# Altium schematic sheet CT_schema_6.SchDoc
size 287 x 160 mm
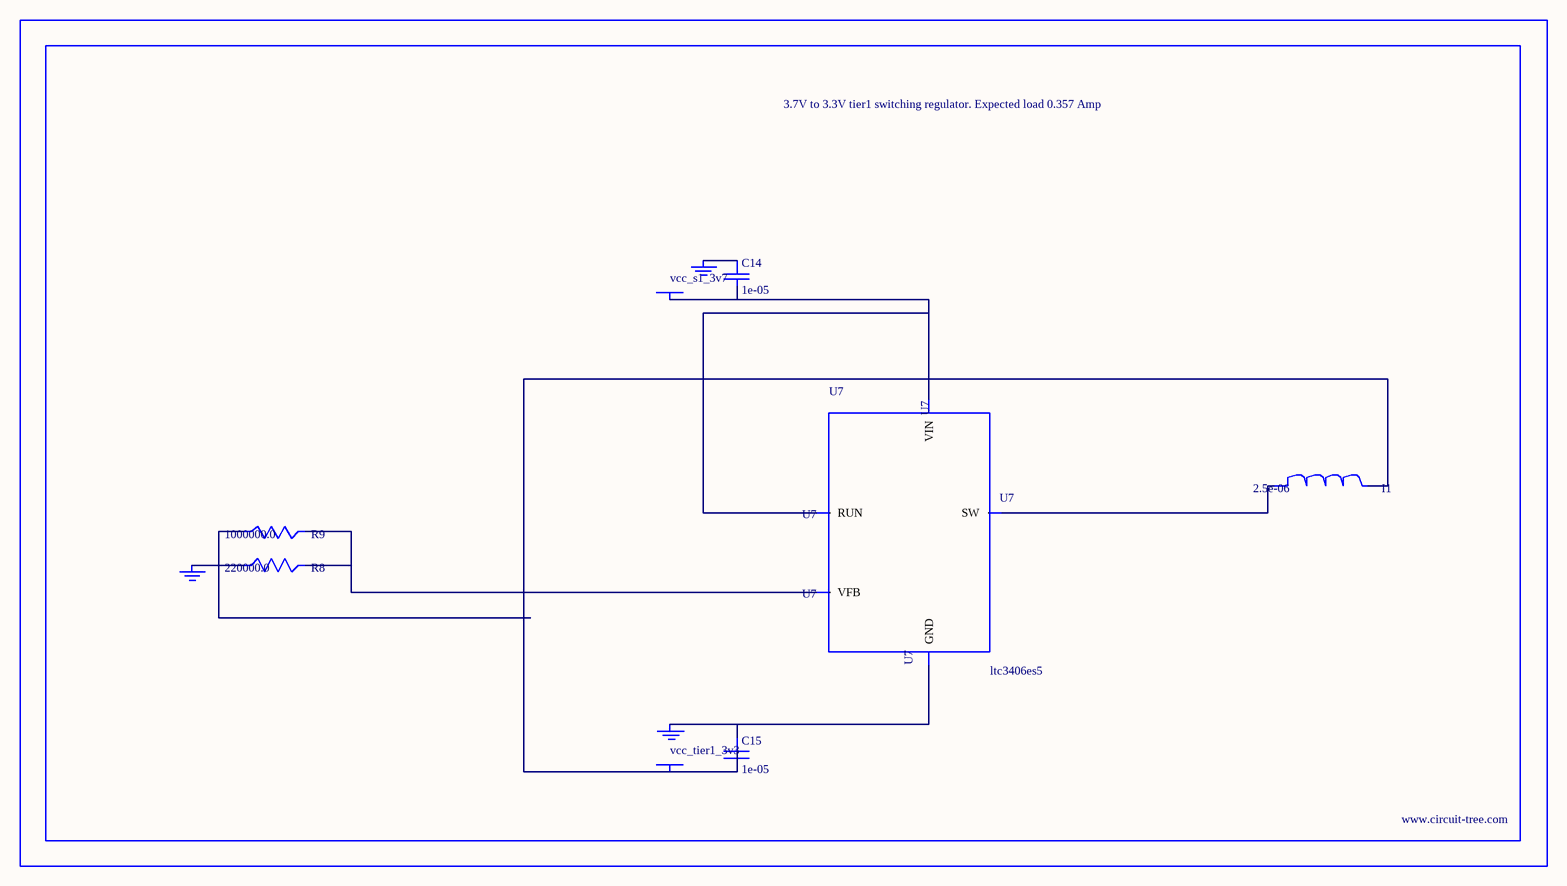
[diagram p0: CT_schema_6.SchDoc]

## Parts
BORDER5  (no value)
C14  1e-05  [C0805]
C15  1e-05  [C0805]
GND_INSTANCE_5_0  (no value)
GND_INSTANCE_5_1  (no value)
GND_INSTANCE_5_2  (no value)
I1  2.5e-06  [DR1040]
POWER_INSTANCE_5_0  vcc_tier1_3v3
POWER_INSTANCE_5_1  vcc_s1_3v7
R8  220000.0  [R0603]
R9  1000000.0  [R0603]
U7  ltc3406es5  [TSOT-23-5]

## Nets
NetC14_1: C14.1 GND_INSTANCE_5_1.0(GND)
NetC14_2: C14.2 POWER_INSTANCE_5_1.0(PWR) U7.1(RUN) U7.4(VIN)
NetC15_1: C15.1 GND_INSTANCE_5_0.0(GND) U7.2(GND)
NetC15_2: C15.2 I1.2 POWER_INSTANCE_5_0.0(PWR) R9.1
NetGND_INSTANCE_5_2_0: GND_INSTANCE_5_2.0(GND) R8.1
NetI1_1: I1.1 U7.3(SW)
NetR8_2: R8.2 R9.2 U7.5(VFB)

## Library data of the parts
BORDER5 = BORDER_PAGE5
C14 C15 = C0805C106K8RACTU
GND_INSTANCE_5_0-GND_INSTANCE_5_2 = GND
I1 = DR1040-2R5-R
POWER_INSTANCE_5_0 POWER_INSTANCE_5_1 = PWR
R8 = RC0603JR-07220KL
R9 = RC0603JR-071ML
